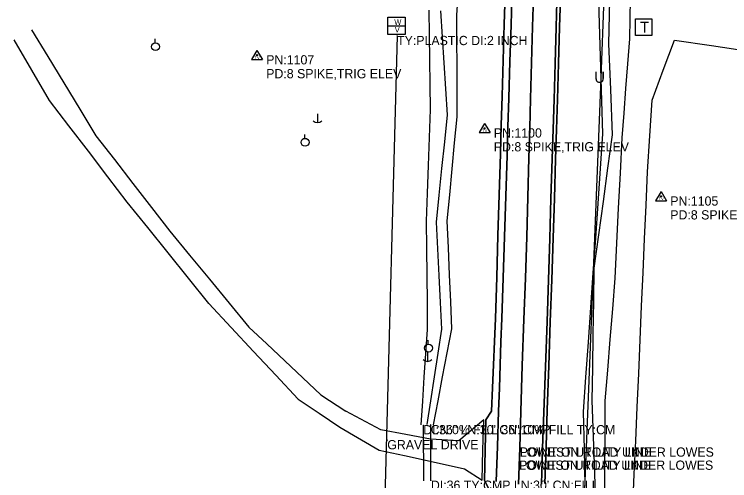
# Model space of a CAD drawing. Extents: x 1445297 to 1476720, y 2042269 to 2057889.
# Drawn here: x 1445801.6 to 1446189, y 2043399.8 to 2043652.1 of the extents above; entities that cross this region are included whole.
import ezdxf

# ---------------------------------------------------------------- set-up
doc = ezdxf.new("R2010")
doc.units = 0
for name, color, linetype in [('S_DITCHLINE', 7, 'Continuous'), ('S_DRG_PT_SYM', 7, 'Continuous'), ('S_DRIVEWAY', 7, 'Continuous'), ('S_EDGE_PAVEMENT', 7, 'Continuous'), ('S_ELECTRIC_UTILITIES_ANNOT', 7, 'Continuous'), ('S_MSC_PT_SYM', 7, 'Continuous'), ('S_PAVEMENT_CROWN', 7, 'Continuous'), ('S_SECONDARY_CTL', 7, 'Continuous'), ('S_SECONDARY_CTL_ANNOT', 7, 'Continuous'), ('S_SHOULDER', 7, 'Continuous'), ('S_SIDE_DRAIN', 7, 'Continuous'), ('S_SIDE_DRAIN_ANNOT', 7, 'Continuous'), ('S_SURVEY_TEXT_ANNOT', 7, 'Continuous'), ('S_TELEPHONE_UTILITIES', 7, 'Continuous'), ('S_TREE', 7, 'Continuous'), ('S_UNDERGROUND_CABLE', 7, 'Continuous'), ('S_UTILITY_POLE', 7, 'Continuous'), ('S_UTL_PT_SYM', 7, 'Continuous'), ('S_WATER_UTILITIES', 7, 'Continuous'), ('S_WATER_UTILITIES_ANNOT', 7, 'Continuous')]:
    doc.layers.add(name, color=color, linetype=linetype)

msp = doc.modelspace()

# ---------------------------------------------------------------- linework, layer by layer
at = {"layer": 'S_DITCHLINE'}
for points in [[(1446028.53, 2043429.99), (1446031.04, 2043442.99), (1446033.55, 2043455.99), (1446036.06, 2043468.99), (1446038.57, 2043481.99), (1446037.93, 2043496.57), (1446037.29, 2043511.15), (1446036.65, 2043525.74), (1446036.01, 2043540.32), (1446037.35, 2043554.39), (1446038.68, 2043568.46), (1446040.02, 2043582.53), (1446041.36, 2043596.6), (1446041.34, 2043610.4), (1446041.32, 2043624.19), (1446041.3, 2043637.98), (1446041.28, 2043651.77), (1446042.71, 2043673.46)], [(1446116.58, 2043384.46), (1446115.91, 2043404.02), (1446115.24, 2043423.58), (1446114.56, 2043443.14), (1446114.84, 2043461.05), (1446115.12, 2043478.96), (1446115.4, 2043496.88), (1446115.68, 2043514.79), (1446118.14, 2043532.81), (1446120.6, 2043550.83), (1446123.07, 2043568.85), (1446125.53, 2043586.87), (1446124.57, 2043611.53), (1446123.61, 2043636.2), (1446124.06, 2043659.83)], [(1446116.58, 2043384.46), (1446115.91, 2043404.02), (1446115.24, 2043423.58), (1446114.56, 2043443.14), (1446114.84, 2043461.05), (1446115.12, 2043478.96), (1446115.4, 2043496.88), (1446115.68, 2043514.79), (1446118.14, 2043532.81), (1446120.6, 2043550.83), (1446123.07, 2043568.85), (1446125.53, 2043586.87), (1446124.57, 2043611.53), (1446123.61, 2043636.2), (1446124.06, 2043659.83)], [(1446121.38, 2043383.66), (1446121.44, 2043403.41), (1446121.5, 2043423.17), (1446121.57, 2043442.93), (1446122.93, 2043459.54), (1446124.29, 2043476.15), (1446125.66, 2043492.76), (1446127.02, 2043509.37), (1446127.94, 2043528.34), (1446128.86, 2043547.3), (1446129.78, 2043566.27), (1446130.7, 2043585.24), (1446131.75, 2043598.63), (1446132.8, 2043612.03), (1446133.84, 2043625.43), (1446134.89, 2043638.83), (1446135.28, 2043660.7)], [(1446121.38, 2043383.66), (1446121.44, 2043403.41), (1446121.5, 2043423.17), (1446121.57, 2043442.93), (1446122.93, 2043459.54), (1446124.29, 2043476.15), (1446125.66, 2043492.76), (1446127.02, 2043509.37), (1446127.94, 2043528.34), (1446128.86, 2043547.3), (1446129.78, 2043566.27), (1446130.7, 2043585.24), (1446131.75, 2043598.63), (1446132.8, 2043612.03), (1446133.84, 2043625.43), (1446134.89, 2043638.83), (1446135.28, 2043660.7)], [(1446021.83, 2043430.04), (1446022.72, 2043442.92), (1446023.62, 2043455.79), (1446024.51, 2043468.66), (1446025.41, 2043481.54), (1446025.27, 2043496.2), (1446025.14, 2043510.85), (1446025.01, 2043525.51), (1446024.88, 2043540.17), (1446025.39, 2043555.29), (1446025.89, 2043570.41), (1446026.4, 2043585.53), (1446026.91, 2043600.65), (1446026.75, 2043614.09), (1446026.58, 2043627.53), (1446026.41, 2043640.96), (1446026.24, 2043654.4)], [(1446025.17, 2043430.14), (1446027.14, 2043443.05), (1446029.12, 2043455.95), (1446031.09, 2043468.86), (1446033.07, 2043481.76), (1446032.33, 2043496.25), (1446031.6, 2043510.74), (1446030.86, 2043525.23), (1446030.13, 2043539.72), (1446031.64, 2043554.22), (1446033.15, 2043568.71), (1446034.66, 2043583.21), (1446036.17, 2043597.71), (1446035.26, 2043611.8), (1446034.35, 2043625.89), (1446033.44, 2043639.99), (1446032.52, 2043654.08)]]:
    msp.add_lwpolyline(points, dxfattribs=at)
at = {"layer": 'S_DRG_PT_SYM'}
for points in [[(1446023.04, 2043429.88), (1446023.04, 2043429.93), (1446023.04, 2043429.88), (1446022.99, 2043429.88), (1446023.04, 2043429.88), (1446023.04, 2043429.83), (1446023.04, 2043429.88), (1446023.09, 2043429.88)], [(1446027.08, 2043429.95), (1446027.08, 2043430), (1446027.08, 2043429.95), (1446027.03, 2043429.95), (1446027.08, 2043429.95), (1446027.08, 2043429.9), (1446027.08, 2043429.95), (1446027.13, 2043429.95)], [(1446027.16, 2043399.86), (1446027.16, 2043399.91), (1446027.16, 2043399.86), (1446027.11, 2043399.86), (1446027.16, 2043399.86), (1446027.16, 2043399.81), (1446027.16, 2043399.86), (1446027.21, 2043399.86)]]:
    msp.add_lwpolyline(points, dxfattribs=at)
at = {"layer": 'S_DRIVEWAY'}
for points in [[(1445810.97, 2043643.68), (1445819.67, 2043629.38), (1445828.37, 2043615.08), (1445837.07, 2043600.78), (1445845.77, 2043586.48), (1445855.79, 2043573.55), (1445865.8, 2043560.61), (1445875.82, 2043547.68), (1445885.84, 2043534.75), (1445896.52, 2043521.8), (1445907.2, 2043508.85), (1445917.88, 2043495.89), (1445928.56, 2043482.94), (1445938.3, 2043473.79), (1445948.04, 2043464.64), (1445957.79, 2043455.48), (1445967.53, 2043446.33)], [(1445955.27, 2043443.98), (1445943.19, 2043456.89), (1445931.12, 2043469.79), (1445919.04, 2043482.69), (1445906.97, 2043495.6), (1445895.91, 2043509.32), (1445884.86, 2043523.04), (1445873.81, 2043536.76), (1445862.76, 2043550.48), (1445852.22, 2043564.26), (1445841.68, 2043578.04), (1445831.14, 2043591.82), (1445820.61, 2043605.6), (1445811.09, 2043621.99), (1445801.58, 2043638.37)], [(1445967.53, 2043446.33), (1445981.18, 2043437.4)], [(1445955.27, 2043443.98), (1445966.6, 2043436.38), (1445977.94, 2043428.78)], [(1445977.94, 2043428.78), (1445999.09, 2043416.34), (1446012.94, 2043413.35), (1446026.8, 2043410.36), (1446045.4, 2043406.29), (1446054.9, 2043400.17), (1446055.37, 2043416.49), (1446055.84, 2043432.81), (1446042.27, 2043421.39), (1446027.04, 2043422.36), (1446013.59, 2043424.84), (1446000.13, 2043427.32), (1445981.18, 2043437.4)]]:
    msp.add_lwpolyline(points, dxfattribs=at)
at = {"layer": 'S_EDGE_PAVEMENT'}
for points in [[(1446062.55, 2043399.3), (1446063.21, 2043418.35), (1446063.87, 2043437.41), (1446064.29, 2043449.93), (1446064.71, 2043462.46), (1446065.13, 2043474.99), (1446065.54, 2043487.52), (1446066.26, 2043509.64), (1446066.98, 2043531.76), (1446067.74, 2043553.73), (1446068.49, 2043575.7), (1446068.92, 2043591.23), (1446069.36, 2043606.75), (1446069.99, 2043626.55), (1446070.63, 2043646.35), (1446071.19, 2043668.11)], [(1446071.19, 2043668.11), (1446070.63, 2043646.35), (1446069.99, 2043626.55), (1446069.36, 2043606.75), (1446068.92, 2043591.23), (1446068.49, 2043575.7), (1446067.74, 2043553.73), (1446066.98, 2043531.76), (1446066.26, 2043509.64), (1446065.54, 2043487.52), (1446065.13, 2043474.99), (1446064.71, 2043462.46), (1446064.29, 2043449.93), (1446063.87, 2043437.41), (1446063.21, 2043418.35), (1446062.55, 2043399.3)], [(1446087, 2043397.93), (1446087.69, 2043417.37), (1446088.38, 2043436.82), (1446089.26, 2043461.35), (1446090.13, 2043485.88), (1446090.84, 2043508.41), (1446091.54, 2043530.93), (1446092.2, 2043552.42), (1446092.85, 2043573.9), (1446093.38, 2043589.94), (1446093.91, 2043605.98), (1446094.44, 2043625.56), (1446094.96, 2043645.15), (1446095.51, 2043666)], [(1446095.51, 2043666), (1446094.96, 2043645.15), (1446094.44, 2043625.56), (1446093.91, 2043605.98), (1446093.38, 2043589.94), (1446092.85, 2043573.9), (1446092.2, 2043552.42), (1446091.54, 2043530.93), (1446090.84, 2043508.41), (1446090.13, 2043485.88), (1446089.26, 2043461.35), (1446088.38, 2043436.82), (1446087.69, 2043417.37), (1446087, 2043397.93)]]:
    msp.add_lwpolyline(points, dxfattribs=at)
at = {"layer": 'S_MSC_PT_SYM'}
for points in [[(1446003.54, 2043421.78), (1446003.54, 2043421.83), (1446003.54, 2043421.78), (1446003.49, 2043421.78), (1446003.54, 2043421.78), (1446003.54, 2043421.73), (1446003.54, 2043421.78), (1446003.59, 2043421.78)], [(1446075.28, 2043417.78), (1446075.28, 2043417.83), (1446075.28, 2043417.78), (1446075.23, 2043417.78), (1446075.28, 2043417.78), (1446075.28, 2043417.73), (1446075.28, 2043417.78), (1446075.33, 2043417.78)], [(1446074.93, 2043410.7), (1446074.93, 2043410.75), (1446074.93, 2043410.7), (1446074.88, 2043410.7), (1446074.93, 2043410.7), (1446074.93, 2043410.65), (1446074.93, 2043410.7), (1446074.98, 2043410.7)]]:
    msp.add_lwpolyline(points, dxfattribs=at)
at = {"layer": 'S_PAVEMENT_CROWN'}
for points in [[(1446074.6, 2043397.98), (1446075.25, 2043417.63), (1446075.91, 2043437.27), (1446076.69, 2043462.14), (1446077.47, 2043487.01), (1446078.32, 2043509.35), (1446079.17, 2043531.69), (1446079.72, 2043553.13), (1446080.27, 2043574.56), (1446080.72, 2043590.54), (1446081.17, 2043606.51), (1446081.68, 2043625.92), (1446082.19, 2043645.33), (1446082.94, 2043667.14)], [(1446082.94, 2043667.14), (1446082.19, 2043645.33), (1446081.68, 2043625.92), (1446081.17, 2043606.51), (1446080.72, 2043590.54), (1446080.27, 2043574.56), (1446079.72, 2043553.13), (1446079.17, 2043531.69), (1446078.32, 2043509.35), (1446077.47, 2043487.01), (1446076.69, 2043462.14), (1446075.91, 2043437.27), (1446075.25, 2043417.63), (1446074.6, 2043397.98)]]:
    msp.add_lwpolyline(points, dxfattribs=at)
at = {"layer": 'S_SECONDARY_CTL'}
for p, q in [((1445932.98, 2043632.65), (1445929.97, 2043627.69)), ((1445932.98, 2043632.65), (1445935.93, 2043627.69)), ((1445929.97, 2043627.69), (1445935.93, 2043627.69)), ((1446056.25, 2043593.08), (1446053.24, 2043588.13)), ((1446056.25, 2043593.08), (1446059.2, 2043588.13)), ((1446053.24, 2043588.13), (1446059.2, 2043588.13)), ((1446151.8, 2043556.25), (1446148.79, 2043551.29)), ((1446151.8, 2043556.25), (1446154.75, 2043551.29)), ((1446148.79, 2043551.29), (1446154.75, 2043551.29))]:
    msp.add_line(p, q, dxfattribs=at)
for centre, radius in [((1445932.98, 2043630.04), 0.311), ((1445932.98, 2043630.04), 0.183), ((1445932.98, 2043630.04), 0.103), ((1446056.25, 2043590.47), 0.311), ((1446056.25, 2043590.47), 0.183), ((1446056.25, 2043590.47), 0.103), ((1446151.8, 2043553.64), 0.311), ((1446151.8, 2043553.64), 0.183), ((1446151.8, 2043553.64), 0.103)]:
    msp.add_circle(centre, radius, dxfattribs=at)
at = {"layer": 'S_SHOULDER'}
for points in [[(1446058.86, 2043394.66), (1446056.22, 2043399.99), (1446056.55, 2043416.39), (1446056.88, 2043432.8), (1446060.07, 2043437.49), (1446060.59, 2043450), (1446061.12, 2043462.52), (1446061.64, 2043475.03), (1446062.17, 2043487.54), (1446062.81, 2043509.97), (1446063.45, 2043532.4), (1446064.14, 2043554.54), (1446064.84, 2043576.69), (1446065.3, 2043592.23), (1446065.76, 2043607.78), (1446066.29, 2043627.27), (1446066.81, 2043646.76), (1446067.51, 2043668.29)], [(1446067.51, 2043668.29), (1446066.81, 2043646.76), (1446066.29, 2043627.27), (1446065.76, 2043607.78), (1446065.3, 2043592.23), (1446064.84, 2043576.69), (1446064.14, 2043554.54), (1446063.45, 2043532.4), (1446062.81, 2043509.97), (1446062.17, 2043487.54), (1446061.64, 2043475.03), (1446061.12, 2043462.52), (1446060.59, 2043450), (1446060.07, 2043437.49), (1446056.88, 2043432.8), (1446056.55, 2043416.39), (1446056.22, 2043399.99), (1446058.86, 2043394.66)], [(1446088.96, 2043398.24), (1446089.55, 2043418.22), (1446090.14, 2043438.2), (1446090.98, 2043461.99), (1446091.83, 2043485.79), (1446092.62, 2043508.46), (1446093.41, 2043531.13), (1446094.03, 2043552.44), (1446094.65, 2043573.75), (1446095.17, 2043589.89), (1446095.7, 2043606.02), (1446096.28, 2043625.58), (1446096.86, 2043645.15), (1446097.47, 2043665.98)], [(1446097.47, 2043665.98), (1446096.86, 2043645.15), (1446096.28, 2043625.58), (1446095.7, 2043606.02), (1446095.17, 2043589.89), (1446094.65, 2043573.75), (1446094.03, 2043552.44), (1446093.41, 2043531.13), (1446092.62, 2043508.46), (1446091.83, 2043485.79), (1446090.98, 2043461.99), (1446090.14, 2043438.2), (1446089.55, 2043418.22), (1446088.96, 2043398.24)]]:
    msp.add_lwpolyline(points, dxfattribs=at)
at = {"layer": 'S_SIDE_DRAIN'}
for p, q in [((1446023.04, 2043429.88), (1446023.13, 2043399.73)), ((1446027.16, 2043399.86), (1446027.08, 2043429.95))]:
    msp.add_line(p, q, dxfattribs=at)
at = {"layer": 'S_TELEPHONE_UTILITIES'}
msp.add_lwpolyline([(1446137.91, 2043640.64), (1446137.91, 2043649.64), (1446146.91, 2043649.64), (1446146.91, 2043640.64)], close=True, dxfattribs=at)
at = {"layer": 'S_TREE'}
for points in [[(1446110.68, 2043396.76), (1446110.27, 2043416.91), (1446109.86, 2043437.07), (1446111.17, 2043455.87), (1446112.48, 2043474.67), (1446113.79, 2043493.47), (1446115.1, 2043512.27), (1446116.41, 2043531.07), (1446117.72, 2043549.87), (1446119.03, 2043568.67), (1446120.34, 2043587.46), (1446119.8, 2043605.38), (1446119.25, 2043623.29), (1446118.71, 2043641.2), (1446118.16, 2043659.12)], [(1446136.5, 2043385.07), (1446137.3, 2043403.26), (1446138.1, 2043421.45), (1446138.9, 2043439.65), (1446139.7, 2043457.84), (1446140.49, 2043476.03), (1446141.29, 2043494.22), (1446142.09, 2043512.41), (1446142.89, 2043530.61), (1446143.69, 2043548.8), (1446144.49, 2043566.99), (1446145.78, 2043586.32), (1446147.08, 2043605.65), (1446153.05, 2043621.9), (1446159.03, 2043638.14), (1446179.17, 2043635.2), (1446199.32, 2043632.27)]]:
    msp.add_lwpolyline(points, dxfattribs=at)
at = {"layer": 'S_UNDERGROUND_CABLE'}
for p, q in [((1446141.2, 2044230.61), (1446119.29, 2043617.64)), ((1446119.29, 2043617.64), (1446109.33, 2043371.71))]:
    msp.add_line(p, q, dxfattribs=at)
at = {"layer": 'S_UTILITY_POLE'}
for p, q in [((1445877.91, 2043636.77), (1445877.91, 2043638.88)), ((1445965.75, 2043598.27), (1445965.75, 2043593.55)), ((1445958.94, 2043585.05), (1445958.94, 2043587.16)), ((1446025.77, 2043473.7), (1446025.77, 2043475.81)), ((1446025.26, 2043469.09), (1446025.26, 2043464.36))]:
    msp.add_line(p, q, dxfattribs=at)
for centre in [(1445878.04, 2043634.63), (1445959.06, 2043582.91), (1446025.9, 2043471.56)]:
    msp.add_circle(centre, 2.13, dxfattribs=at)
for centre in [(1445965.81, 2043596.97), (1446025.32, 2043467.78)]:
    msp.add_arc(centre, 3.41, 226.3972, 313.6028, dxfattribs=at)
at = {"layer": 'S_UTL_PT_SYM'}
for points in [[(1446008.87, 2043640.47), (1446008.87, 2043640.52), (1446008.87, 2043640.47), (1446008.82, 2043640.47), (1446008.87, 2043640.47), (1446008.87, 2043640.42), (1446008.87, 2043640.47), (1446008.92, 2043640.47)], [(1446075.28, 2043417.78), (1446075.28, 2043417.83), (1446075.28, 2043417.78), (1446075.23, 2043417.78), (1446075.28, 2043417.78), (1446075.28, 2043417.73), (1446075.28, 2043417.78), (1446075.33, 2043417.78)], [(1446074.93, 2043410.7), (1446074.93, 2043410.75), (1446074.93, 2043410.7), (1446074.88, 2043410.7), (1446074.93, 2043410.7), (1446074.93, 2043410.65), (1446074.93, 2043410.7), (1446074.98, 2043410.7)]]:
    msp.add_lwpolyline(points, dxfattribs=at)
at = {"layer": 'S_WATER_UTILITIES'}
for p, q in [((1446003.83, 2043650.56), (1446013.25, 2043650.56)), ((1446003.83, 2043641.14), (1446003.83, 2043650.56)), ((1446013.25, 2043650.56), (1446013.25, 2043641.14)), ((1446003.83, 2043645.87), (1446013.25, 2043645.87)), ((1446008.87, 2043640.47), (1446001.92, 2043377.5)), ((1446013.25, 2043641.14), (1446003.83, 2043641.14))]:
    msp.add_line(p, q, dxfattribs=at)

# ---------------------------------------------------------------- texts
at = {"layer": 'S_ELECTRIC_UTILITIES_ANNOT'}
for p in [(1446075.28, 2043412.78), (1446074.93, 2043405.7)]:
    msp.add_text('LOWEST UTILITY LINE', height=5, dxfattribs=at).set_placement(p)
at = {"layer": 'S_SECONDARY_CTL'}
for p in [(1445931.78, 2043628.03), (1446055.04, 2043588.46), (1446150.6, 2043551.63)]:
    msp.add_text('TV', height=1.5, dxfattribs=at).set_placement(p)
at = {"layer": 'S_SECONDARY_CTL_ANNOT'}
for s, p in [('PN:1107', (1445937.98, 2043625.04)), ('PD:8 SPIKE,TRIG ELEV', (1445937.98, 2043617.54)), ('PN:1100', (1446061.25, 2043585.47)), ('PD:8 SPIKE,TRIG ELEV', (1446061.25, 2043577.97)), ('PN:1105', (1446156.8, 2043548.64)), ('PD:8 SPIKE,TRIG ELEV', (1446156.8, 2043541.14))]:
    msp.add_text(s, height=5, dxfattribs=at).set_placement(p)
at = {"layer": 'S_SIDE_DRAIN_ANNOT'}
for s, p in [('DI:36" LN:30\' CN:10% FILL TY:CM', (1446023.04, 2043424.88)), ('CN:0% FILL 36" CMP', (1446027.08, 2043424.95)), ("DI:36 TY:CMP LN:30' CN:FILL", (1446027.16, 2043394.86))]:
    msp.add_text(s, height=5, dxfattribs=at).set_placement(p)
at = {"layer": 'S_SURVEY_TEXT_ANNOT'}
for s, p in [('GRAVEL DRIVE', (1446003.54, 2043416.78)), ('POINT ON ROAD UNDER LOWES', (1446075.28, 2043412.78)), ('POINT ON ROAD UNDER LOWES', (1446074.93, 2043405.7))]:
    msp.add_text(s, height=5, dxfattribs=at).set_placement(p)
at = {"layer": 'S_TELEPHONE_UTILITIES'}
msp.add_text('T', height=6, dxfattribs=at).set_placement((1446140.48, 2043642.14))
at = {"layer": 'S_UTL_PT_SYM'}
msp.add_text('U', height=6, dxfattribs=at).set_placement((1446115.66, 2043615.09))
at = {"layer": 'S_WATER_UTILITIES'}
for s, p in [('W', (1446007.38, 2043646.4)), ('V', (1446007.62, 2043642.34))]:
    msp.add_text(s, height=3, dxfattribs=at).set_placement(p)
at = {"layer": 'S_WATER_UTILITIES_ANNOT'}
msp.add_text('TY:PLASTIC DI:2 INCH', height=5, dxfattribs=at).set_placement((1446008.87, 2043635.47))

doc.saveas('drawing.dxf')
